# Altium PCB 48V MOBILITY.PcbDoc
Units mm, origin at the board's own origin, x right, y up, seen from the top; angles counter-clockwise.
Board outline 151.1 x 58.77 mm, 2 copper layers (Top Layer, Bottom Layer), stack 1.671 mm thick; 66 components, 31 nets, 148 pads, 0 vias.
Unrouted connection lines stored in the file: 123.
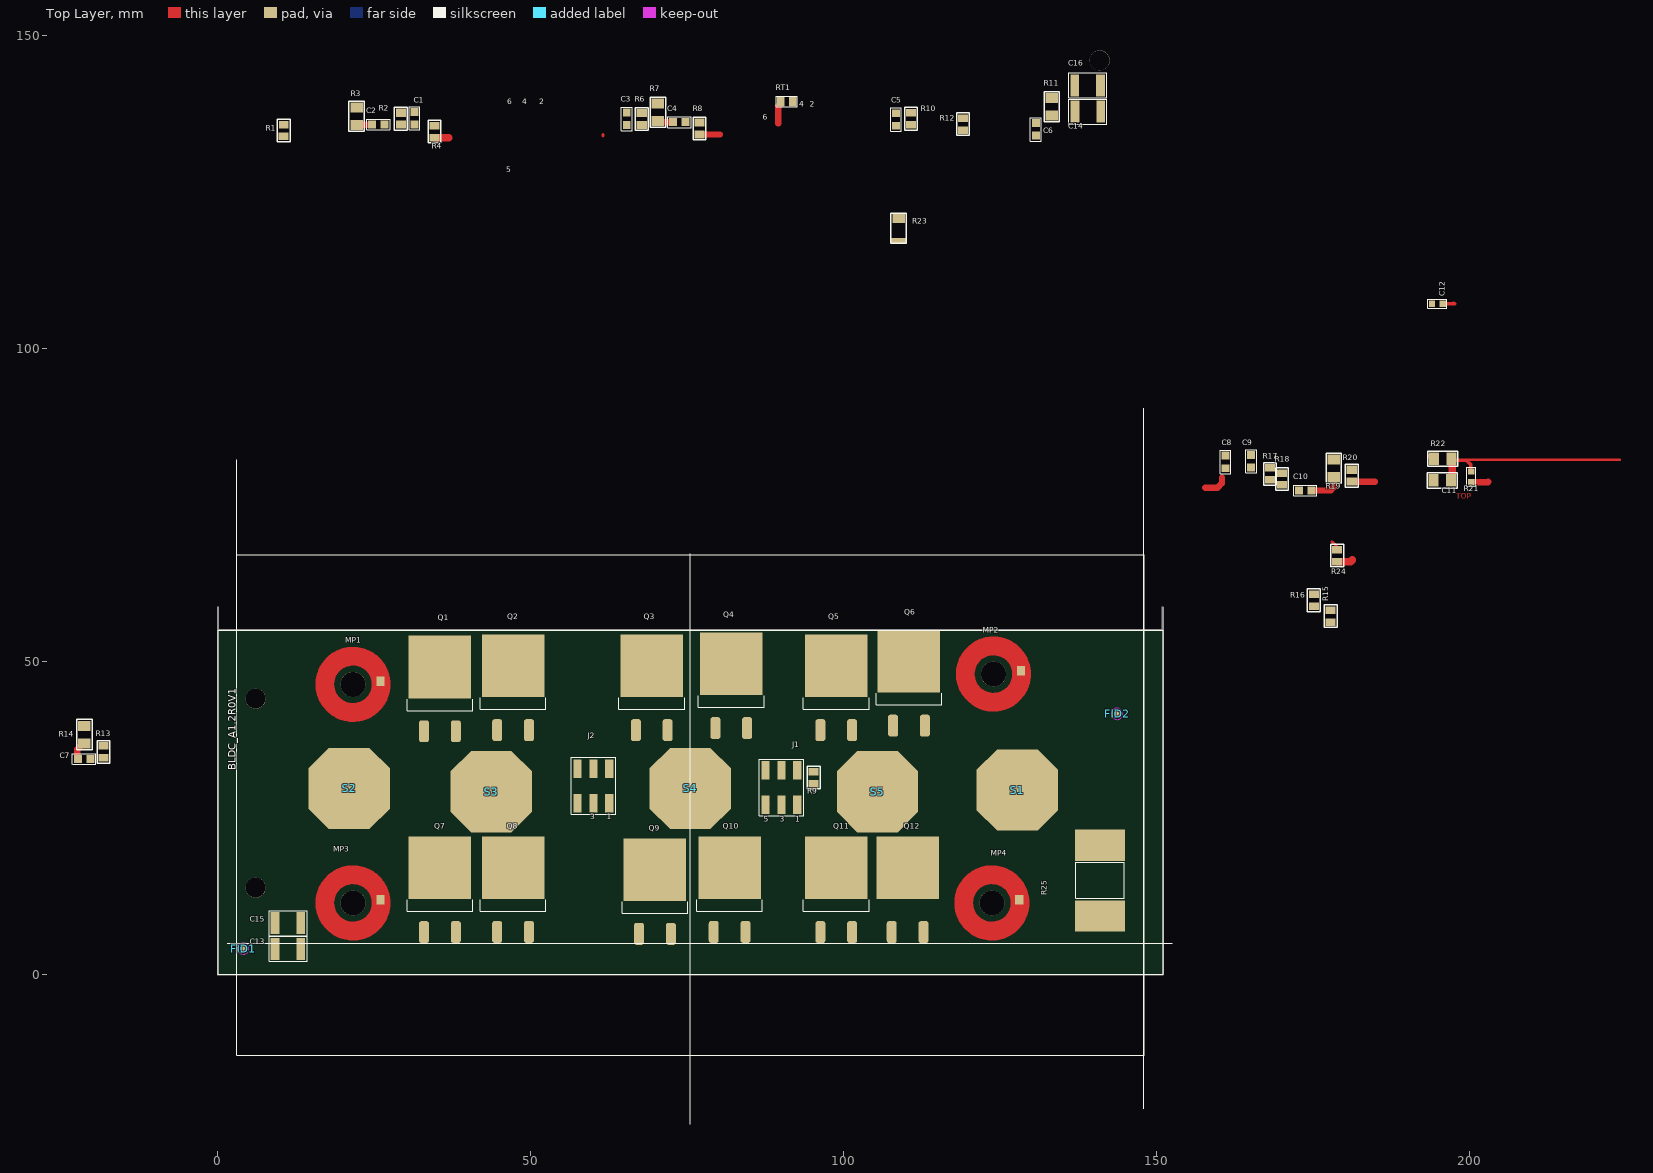
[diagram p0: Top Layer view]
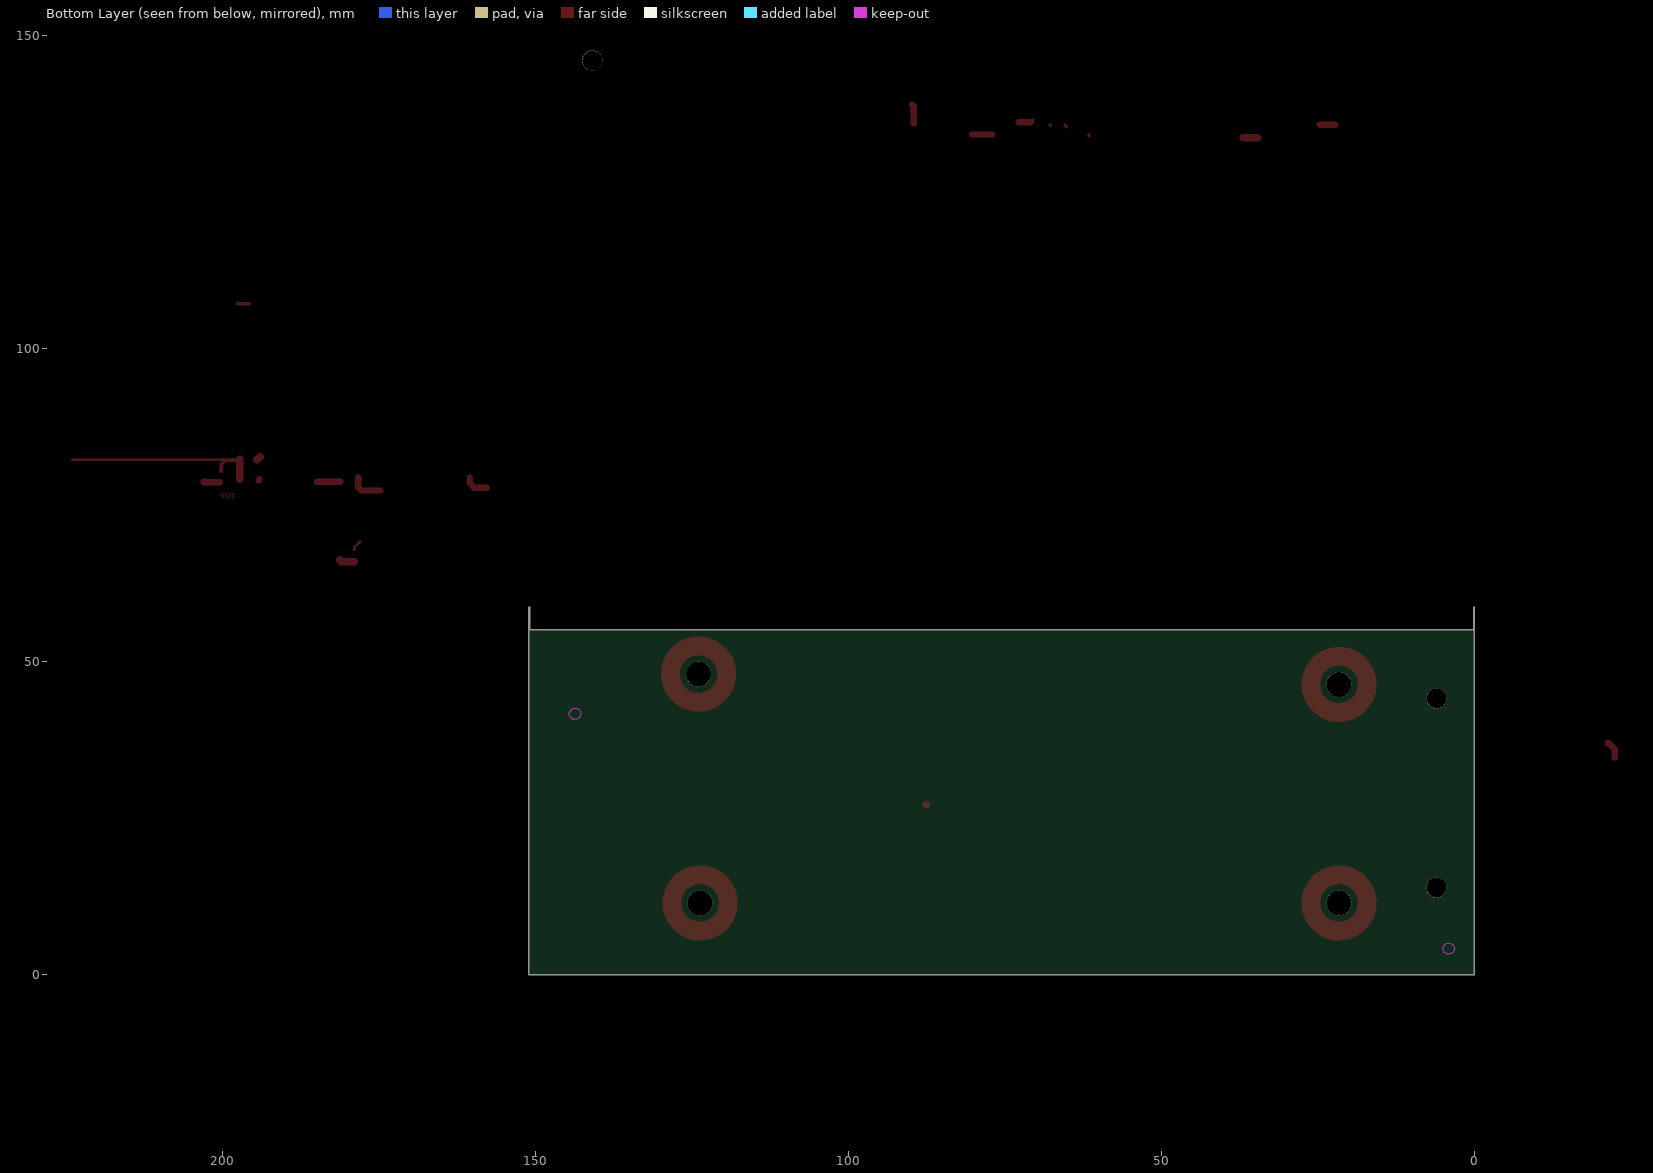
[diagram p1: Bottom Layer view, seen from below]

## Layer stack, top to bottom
Top Solder: solder mask 0.0102, Solder Resist, Dk 3.5
Top Layer: signal copper 0.0356
Dielectric 1: dielectric 1.6, FR-4, Dk 4.8
Bottom Layer: signal copper 0.0356
Bottom Solder: solder mask 0.0102, Solder Resist, Dk 3.5

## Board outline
-0.05,0 ccw(c0,0) 0,-0.05 151,-0.05 ccw(c151,0) 151.05,0 151.05,58.669 ccw(c151,58.669) 150.95,58.669 150.95,55.05 0.05,55.05 0.05,58.669 ccw(c0,58.669) -0.05,58.669

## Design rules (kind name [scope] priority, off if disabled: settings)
Clearance Clearance_3 [InNamedPolygon('TOP_LAYER_S2_P030')] p1: gap=0.254 ignorepadtopadclearanceinfootprint=FALSE
Clearance Clearance_2 [InNamedPolygon('TOP_LAYER_S4_P036')] p2: gap=0.254 ignorepadtopadclearanceinfootprint=FALSE
Clearance "GND POLYGON" [InNamedPolygon('TOP_LAYER_GNDINT_P037')] p3: gap=0.254 ignorepadtopadclearanceinfootprint=FALSE
Clearance Clearance_1 [InNamedPolygon('TOP_LAYER_S2_P030')] p4: gap=0.254 ignorepadtopadclearanceinfootprint=FALSE
Clearance [All] p5: gap=0.254 ignorepadtopadclearanceinfootprint=FALSE
PlaneConnect [All] p1: planeconnectstyle=Direct reliefexpansion=0.508 reliefentries=4 reliefconductorwidth=0.254 reliefairgap=0.254
PolygonConnect [All] p1: connectstyle=Direct reliefconductorwidth=0.254 reliefentries=4 polygonreliefangle="90 Angle" airgapwidth=0.254
RoutingVias [All] p1: holewidth=0.711 width=1.27 viastyle="Through Hole" minholewidth=0.711 minwidth=1.27 maxholewidth=0.711 maxwidth=1.27
SolderMaskExpansion [All] p1: expansion=0.102
Width [All] p1: maxlimit=100 minlimit=0.254 preferedwidth=0.4 minimp=50.000000 maximp=50.000000 favimp=50.000000
29 further rules are at their usual default settings.

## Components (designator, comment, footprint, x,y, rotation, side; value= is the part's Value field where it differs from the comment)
C1 "1nF/100V" CAP_0805 31.419,136.828 r90 top
C2 "10nF/100V" CAP_0805 25.654,135.839 r0 top
C3 "1nF/100V" CAP_0805 65.342,136.731 r90 top
C4 "10nF/100V" CAP_0805 73.769,136.2 r180 top
C5 "1nF/100V" CAP_0805 108.369,136.631 r90 top
C6 "10nF/100V" CAP_0805 130.719,135.056 r90 top
C7 "10nF/100V" CAP_0805 -21.388,34.437 r180 top
C8 "1nF/100V" CAP_0805 161.05,81.9 r90 top
C9 "1nF/100V" CAP_0805 165.137,82.002 r90 top
C10 "10nF/100V" CAP_0805 173.787,77.355 r0 top
C11 "1nF/100V" MY_1206#1 195.656,78.969 r0 top
C12 "10nF/100V" MY_0603 194.906,107.188 r0 top
C13 "10uF/100V" CAP_1812 11.2,4.094 r180 top
C14 "10uF/100V" CAP_1812 139.026,137.907 r180 top
C15 "10uF/100V" CAP_1812 11.2,8.2 r180 top
C16 "10uF/100V" CAP_1812 139.001,142.081 r180 top
FID1 "FID_1MM" FID_40X20D 4.071,4.127 r0 top
FID2 "FID_1MM" FID_40X20D 143.699,41.642 r90 top
J1 "1241050-3" 1241050-3 90.062,29.874 r180 top
J2 "1241050-3" 1241050-3 60.016,30.128 r180 top
MP1 "M5x4mm" "POWER PAD" 21.59,46.362 r0 top
MP2 "M5x4mm" "POWER PAD" 123.952,48.006 r0 top
MP3 "M5x4mm" "POWER PAD" 21.59,11.43 r0 top
MP4 "M5x4mm" "POWER PAD" 123.698,11.43 r0 top
Q1 "HYG085N04LA1D" D2PAK 2.083,164.014 r0 top
Q2 "HYG085N04LA1D" D2PAK 13.78,164.194 r0 top
Q3 "HYG085N04LA1D" D2PAK 35.941,164.194 r0 top
Q4 "HYG085N04LA1D" D2PAK 48.641,164.522 r0 top
Q5 "HYG085N04LA1D" D2PAK 65.422,164.194 r0 top
Q6 "HYG085N04LA1D" D2PAK 77.047,164.915 r0 top
Q7 "HYG085N04LA1D" D2PAK 2.083,131.924 r0 top
Q8 "HYG085N04LA1D" D2PAK 13.78,131.943 r0 top
Q9 "HYG085N04LA1D" D2PAK 36.449,131.641 r0 top
Q10 "HYG085N04LA1D" D2PAK 48.387,131.943 r0 top
Q11 "HYG085N04LA1D" D2PAK 65.422,131.924 r0 top
Q12 "HYG085N04LA1D" "D2 PAK Q12" 110.236,11.909 r0 top
R1 "39R" MY_0805#1 10.516,134.874 r90 top
R2 "10K" MY_0805#2 29.244,136.756 r90 top
R3 "10R" MY_1206#1 22.149,137.119 r90 top
R4 "39R" MY_0805#3 34.619,134.704 r90 top
R6 "10K" MY_0805#2 67.744,136.721 r90 top
R7 "10K" MY_1206#1 70.307,137.77 r90 top
R8 "39R" MY_0805#2 76.994,135.2 r90 top
R9 "39R" MY_0805#3 95.225,31.445 r90 top
R10 "10K" MY_0805#3 110.795,136.754 r90 top
R11 "10K" MY_1206#1 133.243,138.656 r90 top
R12 "39R" MY_0805#3 119.075,135.89 r90 top
R13 "39R" MY_0805#3 -18.289,35.56 r90 top
R14 "10K" MY_1206#1 -21.35,38.31 r90 top
R15 "39R" MY_0805#3 177.846,57.252 r90 top
R16 "10K" MY_0805#3 175.146,59.805 r90 top
R17 "39R" MY_0805#3 168.148,80.01 r90 top
R18 "10K" MY_0805#3 170.053,79.172 r90 top
R19 "100R" MY_1206#1 178.314,80.859 r90 top
R20 "39R" MY_0805#2 181.214,79.703 r90 top
R21 "39R" MY_0603 200.314,79.528 r90 top
R22 "10K" MY_1206#1 195.732,82.423 r0 top
R23 "100R" MY_1206#2 108.769,119.229 r90 top
R24 "39R" MY_0805#3 178.892,66.929 r90 top
R25 "0.5mΩ ±1% 5931" "CURRENT SENSE RESISTORS_5931" 140.97,14.986 r270 top
RT1 "10K" RES_0805 90.907,139.497 r0 top
S1 "M4x20mm" "15MM SPACER"#1 57.296,27.178 r0 top
S2 "M4x20mm" "15MM SPACER"#2 -53.783,26.976 r0 top
S3 "M4x20mm" "15MM SPACER"#3 -29.758,26.924 r0 top
S4 "M4x20mm" "15MM SPACER"#4 5.074,27.432 r0 top
S5 "M4x20mm" "15MM SPACER"#5 34.014,26.924 r0 top

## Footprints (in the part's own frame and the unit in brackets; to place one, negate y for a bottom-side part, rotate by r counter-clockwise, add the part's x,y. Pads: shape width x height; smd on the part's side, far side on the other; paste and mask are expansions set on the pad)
"15MM SPACER"#1 [mm]
  oct 13x13 smd: 1(70.466,2.286)
  body extent 68.77,-1.71 76.77,6.28, height 15.2
"15MM SPACER"#2 [mm]
  oct 13x13 smd: 1(74.771,2.742)
  body extent 68.77,-1.71 76.77,6.28, height 15.2
"15MM SPACER"#3 [mm]
  oct 13x13 smd: 1(73.446,2.286)
  body extent 68.77,-1.71 76.77,6.28, height 15.2
"15MM SPACER"#4 [mm]
  oct 13x13 smd: 1(70.426,2.286)
  body extent 68.77,-1.71 76.77,6.28, height 15.2
"15MM SPACER"#5 [mm]
  oct 13x13 smd: 1(71.396,2.286)
  body extent 68.77,-1.71 76.77,6.28, height 15.2
1241050-3 [mm] "1241050-3"
  rect 1.3x3 smd: 1(-2.54,-2.754) 2(-2.54,2.754) 3(0,-2.754) 4(0,2.754) 5(2.54,-2.754) 6(2.54,2.754)
  silkscreen extent -3.81,-4.55 3.53,4.5, body extent -3.81,-3.75 3.81,3.75, height 9.57
CAP_0805 [mm] "Ceramic Capacitor"
  rect 1.27x1.27 smd mask+0.076: 1(-1,0) 2(1,0)
  silkscreen extent -1.86,-0.86 1.86,0.86, body extent -1,-0.62 1,0.63, height 0.78
CAP_1812 [mm] "CAP_1812"
  rect 1.4x3.51 smd: 1(-2.057,0) 2(2.057,0)
  silkscreen extent -3.05,-2 3.01,2, body extent -2.25,-1.6 2.25,1.6, height 1.1
"CURRENT SENSE RESISTORS_5931" [mm]
  rect 5x8 smd: 1(-5.65,0) 2(5.65,0)
  silkscreen extent -2.95,-3.89 2.84,3.86, body extent -7.5,-3.87 7.5,3.88, height 1.13
"D2 PAK Q12" [mm]
  rrect50% 1.6x3.5 smd: 1(-2.54,-5.137) 2(2.54,-5.137)
  rect 10x10 smd paste-7: 3(0,5.138)
  body extent -5,-4.95 5,10, height 4.51
D2PAK [mm]
  rrect50% 1.6x3.5 smd: 1(30.861,-125.152) 2(35.941,-125.152)
  rect 10x10 smd paste-7: 3(33.401,-114.877)
  silkscreen extent 28.15,-121.85 38.65,-120, body extent 28.4,-124.97 38.4,-110.02, height 4.51
FID_40X20D [mm]
  round 1 smd mask+0: ""(0,0)
  Keep-Out Layer circle w0.05: c0,0 r0.9
MY_0603 [mm]
  rect 1x1.1 smd: 1(-0.85,0) 2(0.85,0)
  silkscreen extent -1.52,-0.71 1.52,0.71, body extent -0.8,-0.4 0.8,0.4, height 0.44
MY_0805#1 [mm] "Resister"
  rect 1.2x1.6 smd: 1(-0.95,0)
  rect 1.2x1.5 smd: 2(0.95,0)
  silkscreen extent -1.8,-1.02 1.8,1.02, body extent -1,-0.62 1,0.63, height 0.59
MY_0805#2 [mm]
  rect 1.3x1.6 smd: 1(-0.95,0) 2(0.95,0)
  silkscreen extent -1.8,-1.02 1.8,1.02, body extent -1,-0.62 1,0.63, height 0.59
MY_0805#3 [mm]
  rect 1.2x1.6 smd: 1(-0.95,0) 2(0.95,0)
  silkscreen extent -1.8,-1.02 1.8,1.02, body extent -1,-0.62 1,0.63, height 0.59
MY_1206#1 [mm]
  rect 1.6x2 smd: 1(-1.375,-0.025) 2(1.425,-0.025)
  silkscreen extent -2.39,-1.24 2.44,1.19, body extent -1.57,-0.83 1.63,0.77, height 0.59
MY_1206#2 [mm]
  rect 1x2.5 smd: 1(-2,-0.025)
  rect 1.4x2 smd: 2(1.6,-0.025)
  silkscreen extent -2.39,-1.24 2.44,1.19, body extent -1.57,-0.83 1.63,0.77, height 0.59
"POWER PAD" [mm]
  rect 1.3x1.5 smd mask+0.076: 1(4.379,0.508)
  round 4 hole 4 unplated: ""(0,0)
  Top Layer circle w3: c0,0 r4.5
RES_0805 [mm] "Resister"
  rect 1.2x1.5 smd mask+0.076: 1(0.95,0) 2(-0.95,0)
  silkscreen extent -1.7,-0.84 1.7,0.89, body extent -1,-0.63 1,0.62, height 0.5

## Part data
C1 C2 C3 C4 C5 C6 C7 C8 C9 C10 C11 C12: library part CAP_33pF-50V-5%-0805, "33pF ±5% 50V Ceramic Capacitor C0G, NP0 0805 (2012 Metric)", Alternate Part Number-1=NA, Case/Package=0805, Manufacturer=Samsung, Manufacturer Part Number=CL21C330JBANNNC, Supplier Part Number-1=0805N330J500CT
C13 C14 C15 C16: library part CAP_2.2uF-25V-10%-0805, "2.2µF ±10% 25V Ceramic Capacitor X7R 0805 (2012 Metric)", Alternate Part Number-1=NA, Case/Package=0805, Manufacturer=KEMET, Manufacturer Part Number=CL21B225KAFNFNE, Supplier Part Number-1=CL21A225KAFNNNE
FID1 FID2: "Fiducial 40 mil Diameter and 120 mil Mask"
J1 J2: "Connector", Manufacturer_Name="TE Connectivity", Mouser Part Number=571-1241050-3
MP1 MP2 MP3 MP4: library part 7466105R, "WP-SMBU SMT Internal blind-hole thread with pins, OD 9mm, M5x4mm, 70A", Manufacturer="Wurth Elektronik", Operating Temperature="-55 to +150degC", Rated Current=70A
Q1 Q2 Q3 Q4 Q5 Q6 Q7 Q8 Q9 Q10 Q11 Q12: library part IRFRC20, "HEXFET Power MOSFET"
R1 R4 R8 R9 R12 R13 R15 R16 R17 R18 R20 R21 R22: library part RES_39R-3W-5%-TH, "39 Ohms ±5% 3W Through Hole Resistor Axial Flame Proof, Safety Wirewound", Alternate Part Number-1=NA, Case/Package=TH, Manufacturer="Stackpole Electronics", Manufacturer Part Number=RWM041039R0JR15E1, Supplier Part Number-1=72-RWM410-39-5
R2 R6 R10: library part RES_10K-0.1W-1%-0603, "10 kOhms ±1% 0.1W, 1/10W Chip Resistor 0603 (1608 Metric) Automotive AEC-Q200 Thick Film", Alternate Part Number-1=0603WAJ0103T5E, Case/Package=0603, Manufacturer=Walsin, Manufacturer Part Number=WR06X1002FTL
R3 R7 R11 R14 R19 R23: library part RES_100R-0.1W-1%-0603, "100 Ohms ±1% 0.1W, 1/10W Chip Resistor 0603 (1608 Metric) Thick Film", Alternate Part Number-1=MR06X1000FTL, Case/Package=0603, Manufacturer=Walsin, Manufacturer Part Number=WR06X1000FTL, Supplier Part Number-1=WALSIN:WR06X1000FTL
R24: library part RES_39R-3W-5%-TH, "390 Ohms ±5% 3W Through Hole Resistor Axial Flame Proof, Safety Wirewound", Alternate Part Number-1=NA, Case/Package=TH, Manufacturer="Stackpole Electronics", Manufacturer Part Number=RWM041039R0JR15E1, Supplier Part Number-1=72-RWM410-39-5
R25: library part CR0603-JW-150ELF, "Resistor", Manufacturer_Name=Bourns
RT1: library part RT_10K-0805, "NTC Thermistor 10k 0805 (2012 Metric)", Alternate Part Number-1=NA, Case/Package=0805, Manufacturer="Vishay BCcomponents", Manufacturer Part Number=NCP21XV103J03RA
S1 S2 S3 S4 S5: library part 9774010482, "WA-SMSI SMT Steel Spacer, internal Thread, OD 8.2mm, M4x1mm", Manufacturer="Wurth Elektronik", Operating Temperature="-55 to +150degC"

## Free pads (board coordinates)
  round 3.2 hole 3.2 unplated: ""(6.023,13.867) ""(6.023,44.073) ""(140.919,146.079)

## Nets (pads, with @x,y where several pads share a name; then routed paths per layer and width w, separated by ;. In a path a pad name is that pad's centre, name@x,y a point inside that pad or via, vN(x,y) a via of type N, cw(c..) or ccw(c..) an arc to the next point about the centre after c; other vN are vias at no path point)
GNDINT: C14.1 C16.1 J1.3 R25.1 RT1.1 S1.1
NetC1_2: C1.2 J2.3 R1.2 R2.2 R4.2
NetC2_1: C2.1 R3.1 | length 2.5
  Top Layer w1: R3.1 22.221,135.792 24.607,135.792 C2.1
NetC3_2: C3.2 J2.1 R6.2 R8.2
NetC4_2: C4.2 R7.1 | length 2.5
  Top Layer w0.4: R7.1@70.469,136.575 R7.1@70.845,136.2
  Top Layer w1: R7.1@70.845,136.2 C4.2
NetC5_2: C5.2 J1.1 R9.2 R10.2 R12.2
NetC6_2: C6.2 R11.1
NetC7_2: C7.2 R14.1 | length 2.8
  Top Layer w1: C7.2@-22.455,34.677 -22.455,36.005 -21.524,36.935 R14.1
NetC8_2: C8.2 J2.6 R13.2 R15.2 R16.2
NetC9_2: C9.2 J2.4 R17.2 R18.2 R20.2
NetC10_2: C10.2 R19.1 | length 5.3
  Top Layer w1: C10.2 177.866,77.355 178.339,77.828 R19.1@178.339,79.428
NetC11_2: C11.2 J1.4 R21.2 R22.2 R24.2 | length 34.5
  Top Layer w0.4: 178.049,69.178 178.994,68.234 R24.2@178.994,67.879 ; C11.2@196.844,79.181 C11.2 ; R22.2@197.304,82.297 R22.2@197.417,82.184 ; 199.517,82.184 199.617,82.285 224.023,82.285 ; R21.2@200.223,80.469 R21.2 R21.2@200.364,80.378
  Top Layer w0.6: R22.2@197.417,82.184 199.517,82.184 200.223,81.478 R21.2@200.223,80.469
  Top Layer w0.7: C11.2 C11.2@197.28,79.142
  Top Layer w1.2: C11.2@197.28,79.142 R22.2@197.28,82.297
NetC12_2: C12.2 R23.1 | length 2.1
  Top Layer w0.5: C12.2 195.761,107.193 197.42,107.193 197.676,107.193 197.681,107.198 ; 197.42,107.24 197.505,107.325
NetJ1_5: J1.5 RT1.2 | length 3.1
  Top Layer w1: 89.554,136.006 89.554,136.26 89.554,138.716 RT1.2@89.844,139.006
NetQ1_1: Q1.1 R1.1
NetQ2_1: Q2.1 R4.1 | length 2.6
  Top Layer w0.4: 36.867,133.754 37.114,134
  Top Layer w1.2: R4.1 36.867,133.754
NetQ3_1: Q3.1
NetQ4_1: Q4.1 R8.1 | length 3.6
  Top Layer w0.4: 80.214,134.25 80.464,134
  Top Layer w1: R8.1 80.214,134.25
NetQ5_1: Q5.1 R9.1
NetQ6_1: Q6.1 R12.1
NetQ7_1: Q7.1 R13.1
NetQ8_1: Q8.1 R15.1
NetQ9_1: Q9.1 R17.1 | length 3.9
  Top Layer w1: 157.81,77.765 159.763,77.765 160.464,78.466 160.464,79.416
NetQ10_1: Q10.1 R20.1 | length 3.8
  Top Layer w1: R20.1@181.214,78.753 184.88,78.753 184.934,78.699 184.934,78.741
NetQ11_1: Q11.1 R21.1 | length 2.6
  Top Layer w1: R21.1@200.489,78.678 202.974,78.678 203.024,78.728
NetQ12_1: Q12.1 R24.1 | length 2.5
  Top Layer w1.2: R24.1@178.994,65.979 181.089,65.979 181.289,66.179 181.289,66.309
S2: C1.1 C2.2 J2.5 Q1.2 Q2.2 Q7.3 Q8.3 R2.1 R14.2 S3.1
S3: C3.1 C4.1 J2.2 Q3.2 Q4.2 Q9.3 Q10.3 R6.1 R19.2 S4.1 | length 0.7
  Top Layer w0.5: 61.549,134 61.549,134.261 ; C3.1@65.13,135.438 65.342,135.65 C3.1@65.402,135.71 ; R6.1@67.684,135.71 R6.1
S4: C5.1 C6.1 J1.2 Q5.2 Q6.2 Q11.3 Q12.3 R10.1 R23.2 S5.1
SHUNT+: C7.1 C8.1 C9.1 C10.1 C11.1 C12.1 C13.1 C15.1 J1.6 MP3.1 MP4.1 Q7.2 Q8.2 Q9.2 Q10.2 Q11.2 Q12.2 R16.1 R18.1 R22.1 R25.2 | length 1
  Top Layer w1: C11.1@194.102,79.123 C11.1
  Top Layer w1.2: J1.6 J1.6@87.53,27.113 ; R22.1@194.024,82.731 R22.1 R22.1@194.538,82.218
VDSS: C13.2 C14.2 C15.2 C16.2 MP1.1 MP2.1 Q1.3 Q2.3 Q3.3 Q4.3 Q5.3 Q6.3 R3.2 R7.2 R11.2 S2.1
pads on no net: FID1. FID2. MP1. MP2. MP3. MP4.

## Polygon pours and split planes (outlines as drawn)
no net on Top Solder "Top Solder-No Net" (solid): 14.975,10.019
no net on Top Layer "TOP_LAYER_NONET_P033" (solid, pour order 33): 136.992,11.297

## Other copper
Top Layer:
  pour cut-out: 106.407,134.736
  text "TOP" at 197.917,75.743 h1.5

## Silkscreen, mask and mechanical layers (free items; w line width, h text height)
Top Overlay:
  lines w0.1: 1.524,5 152.524,5 ; 3,-8.992 3,82.22 ; 3.048,67.046 3.048,-12.954 148.048,-12.954 ; 3.048,67.056 148.048,67.056 148.048,-12.944 ; 75.5,-23.978 75.5,67.234 ; 148,-21.488 148,90.5 ; 0,0 151,0 151,55 0,55 0,0
  text "6" at 46.269,138.77 h1.5
  text "4" at 48.644,138.772 h1.5
  text "2" at 51.344,138.77 h1.5
  text "4" at 92.947,138.379 h1.5
  text "2" at 94.564,138.362 h1.5
  text "6" at 87.094,136.281 h1.5
  text "5" at 46.119,127.874 h1.5
  text "BLDC_A1.2R0V1" at 3.226,32.614 h2 r90
  text "3" at 59.541,24.478 h1.5
  text "1" at 62.141,24.478 h1.5
  text "5" at 87.212,24.049 h1.5
  text "3" at 89.762,24.059 h1.5
  text "1" at 92.237,24.049 h1.5
Mechanical 2:
  lines w0.1: 0,45.3 0,0 151,0 151,45.25 ; 1.636,41.602 146.936,41.602 ; 1.861,41.102 141.686,41.102 ; 145.748,50.492 150.995,45.245 ; 151,0.5 151,51
Mechanical 8:
  lines w0.1: -18.963,41.454 -19.407,41.011 -22.493,41.011 -22.688,40.817 -22.688,39.142 -22.448,38.903 -18.873,38.903 -18.086,39.69 ; 16.789,9.271 28.042,9.271 29.007,10.236 ; 50.845,132.379 50.927,132.461 52.964,132.461 53.498,131.928 ; 91.837,29.374 91.837,25.867 92.329,25.375 93.58,25.375 93.744,25.211 ; 93.869,133.006 94.044,133.181 95.519,133.181 ; 139.834,83.178 149.479,83.178 ; 155.316,83.444 155.951,82.809 171.089,82.809 172.489,81.409 176.064,81.409 179.857,81.409 181.661,83.213 182.009,83.561 192.291,83.561 192.589,83.859 ; 166.416,61.544 177.82,61.544 178.691,60.673 ; 178.087,70.772 178.774,71.459 188.544,71.459 ; 200.246,83.878 224.061,83.878
Mechanical 11:
  lines w0.1: -21.099,35.118 -19.711,35.118 -19.711,33.848 ; 13.195,3.3 14.284,4.389 14.284,6.477 ; 15.672,5.207 16.379,4.5 17.928,4.5 20.726,4.5 ; 20.574,4.496 20.726,4.496 21.438,5.207 ; 20.93,3.429 20.93,6.68 21.603,7.354 21.959,7.354 22.162,7.354 30.128,7.354 31.004,8.23 ; 105.588,8.128 113.467,8.128 113.732,7.863 ; 144.139,80.584 144.864,81.31 147.604,81.31 148.529,80.384 156.267,80.384 156.515,80.137 156.515,76.663 157.199,75.978 159.795,75.978 161.297,75.978 162.077,76.759 162.077,80.112 162.744,80.778 163.22,81.255 167.662,81.255 168.439,80.478 168.439,78.928 168.614,78.753 169.339,78.753 ; 168.413,59.538 176.013,59.538 176.346,59.205 176.346,55.324 ; 168.971,78.753 173.145,78.753 173.439,78.459 173.439,78.308 173.439,76.419 173.705,76.153 186.108,76.153 186.664,76.709 186.664,80.359 187.783,81.478 190.464,81.478 193.046,81.478 193.046,83.391 193.314,83.659 195.001,83.659 195.539,83.122 195.539,75.584 195.82,75.303 204.908,75.303 205.181,75.577 205.181,79.345 205.181,80.302 206.533,81.653 210.013,81.653 ; 182.982,63.094 182.982,66.167 186.944,70.129

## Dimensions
151.613,0.051 to 151,51 on Mechanical 1
-0.05,0 to 151,0 on Mechanical 1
